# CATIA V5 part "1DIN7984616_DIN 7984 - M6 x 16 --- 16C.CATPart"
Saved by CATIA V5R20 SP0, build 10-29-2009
Part number: 1DIN7984616_DIN 7984 - M6 x 16 --- 16C
Revision: ANY
Definition: UNKNOWN
Nomenclature: 1DIN7984616_DIN 7984 - M6 x 16 --- 16C
Source: Unknown
Bounding box of the stored display mesh (mm): x 0 to 20, y -5 to 5, z -5 to 5
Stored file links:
  C:\Users\Utente\Desktop\IO LAVORO\3D X SITO CF\CUMSA\3D files PW\pw101430\pw101430_ejection\1DIN7984616_DIN 7984 - M6 x 16 --- 16C.CATPart
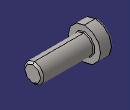
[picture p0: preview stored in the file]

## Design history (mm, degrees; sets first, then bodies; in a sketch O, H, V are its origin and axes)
Body1 "Hex" (main body)
  Solid1: solid without history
